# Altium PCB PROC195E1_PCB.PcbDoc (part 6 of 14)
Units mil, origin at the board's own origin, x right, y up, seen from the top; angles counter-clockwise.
Board outline 3110.24 x 2500 mil, 10 copper layers (Top Layer, L02_GND1, L03_SIG1, L04_GND2, L05_PWR1, L06_PWR2, L07_GND3, L08_SIG2, L09_GND4, Bottom Layer), stack 66.407 mil thick; 571 components, 538 nets, 6726 pads, 1286 vias.
Unrouted connection lines stored in the file: 4.
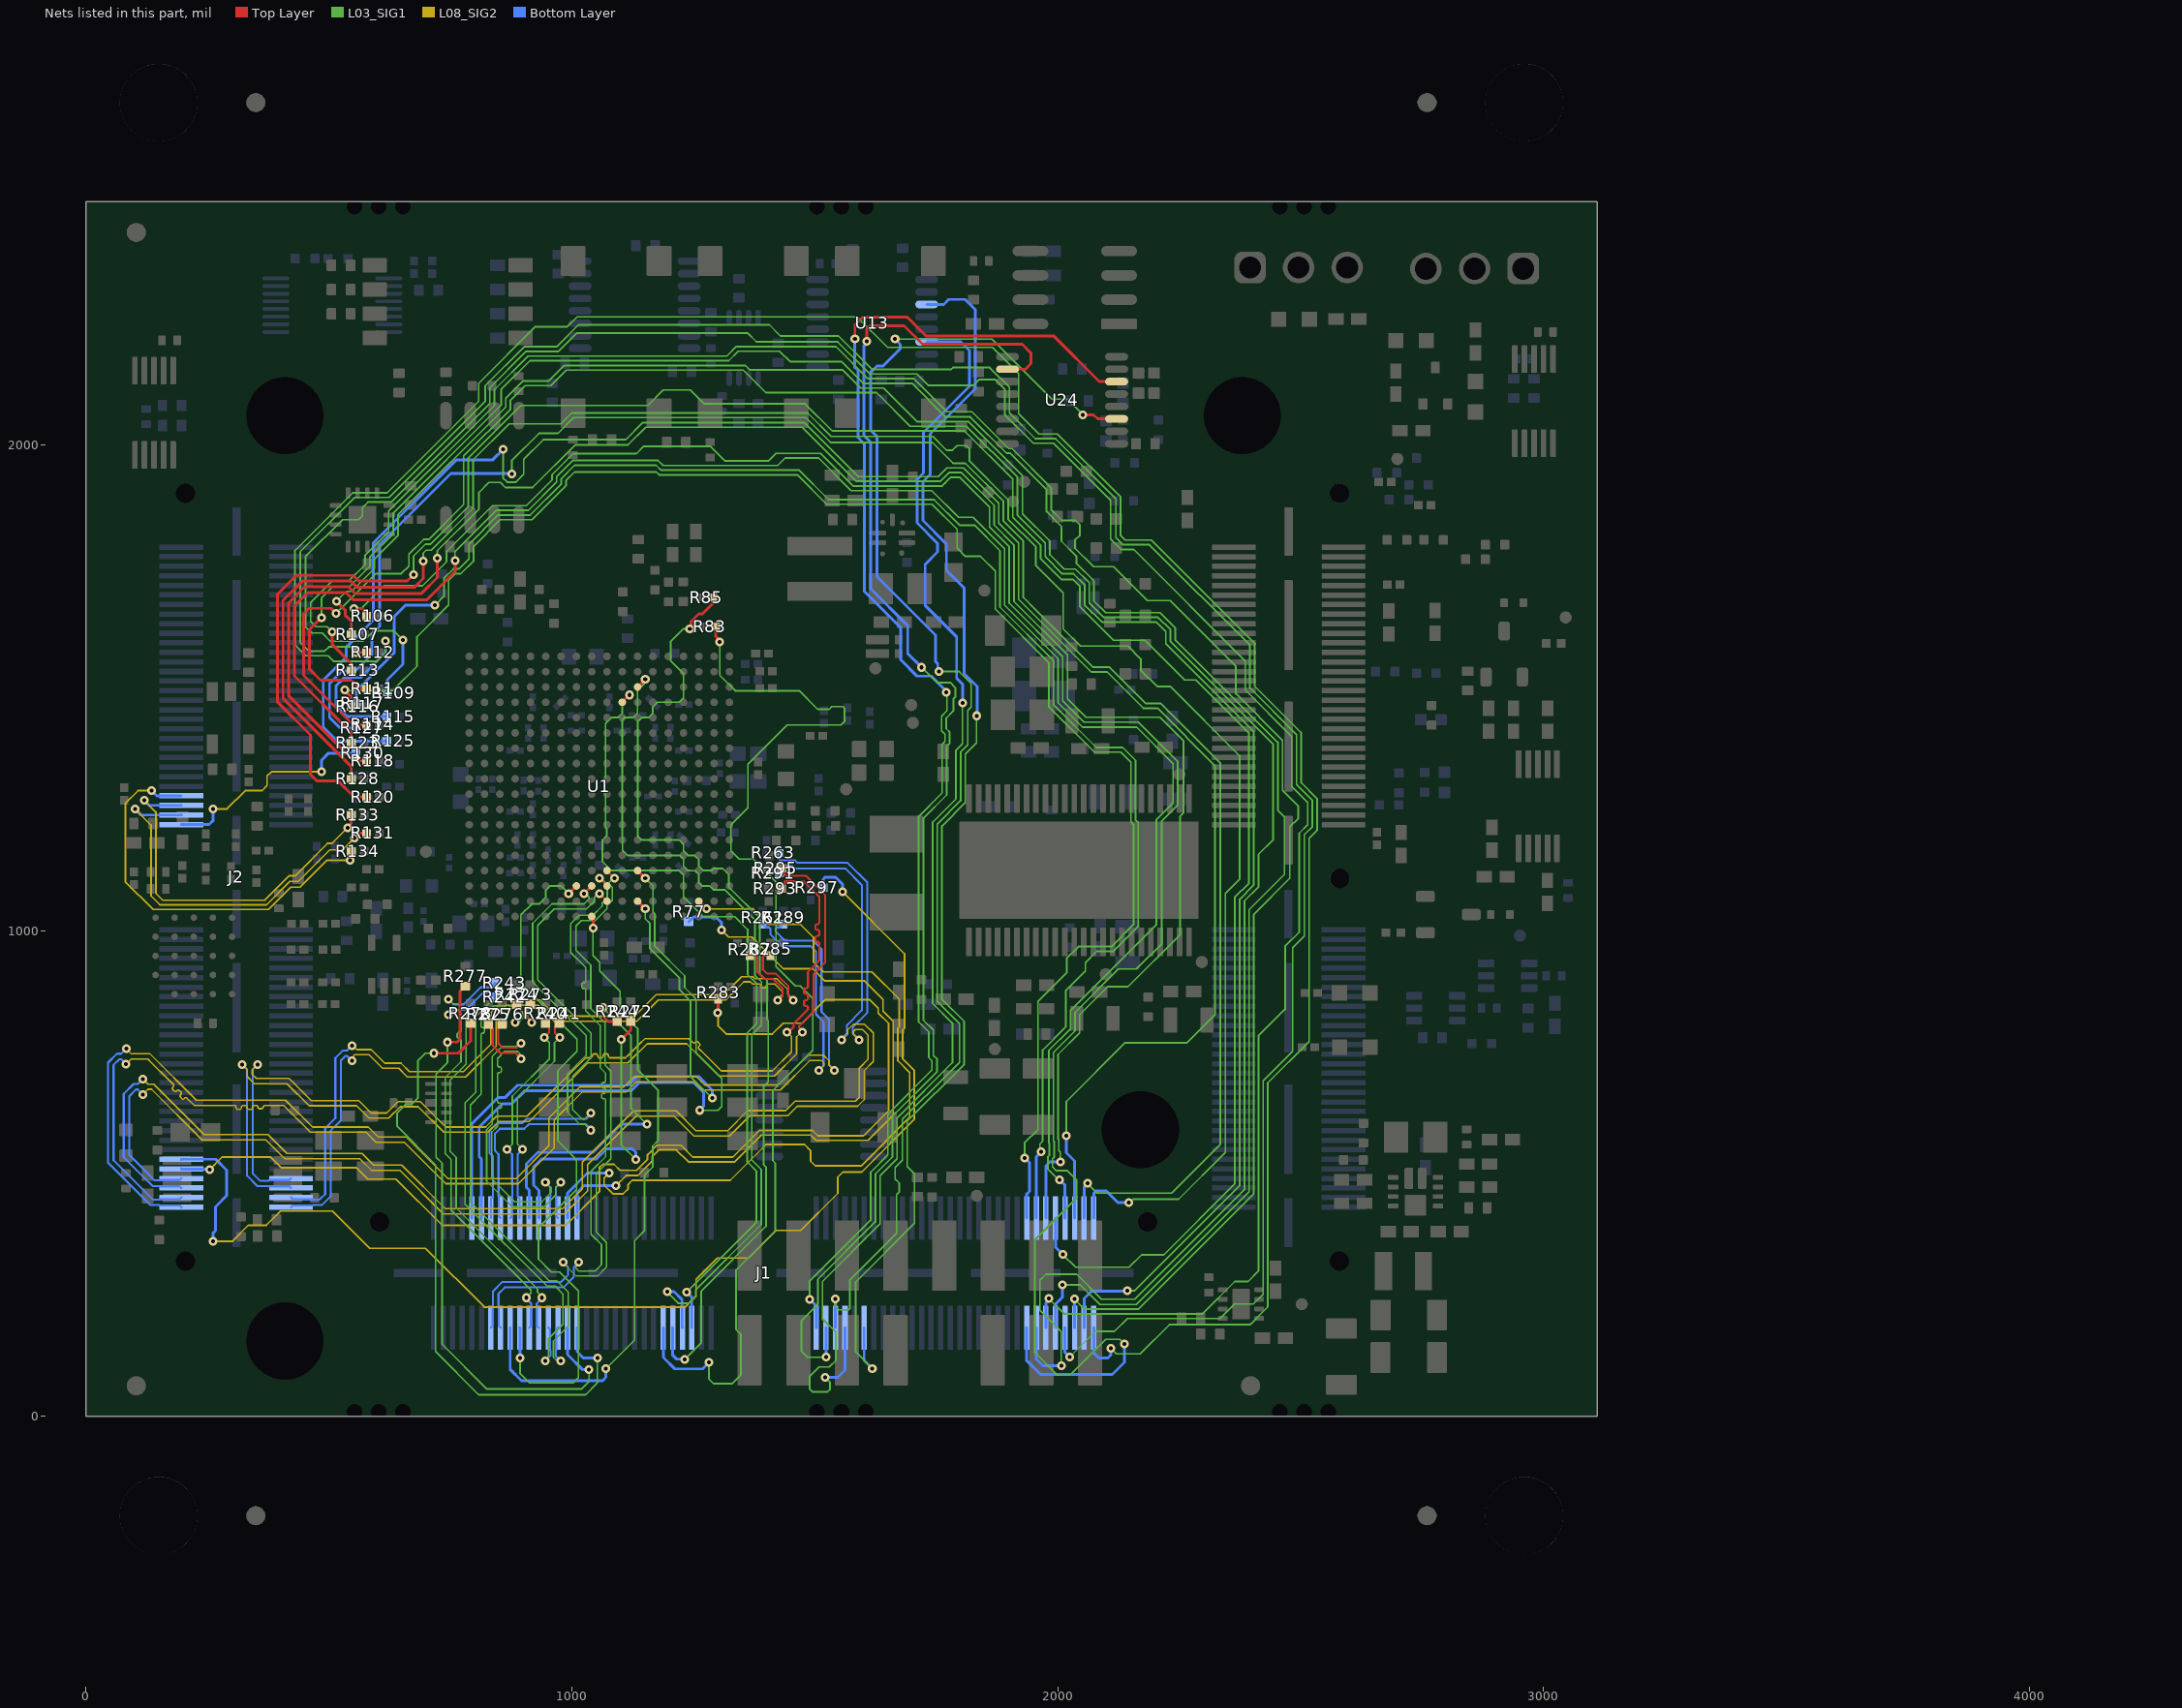
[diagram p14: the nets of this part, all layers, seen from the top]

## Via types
v1: diameter 18, hole 8, Top Layer to Bottom Layer, tented both sides, 1226 vias
v2: diameter 19.68, hole 7.87, Top Layer to Bottom Layer, tented top, 54 vias
v3: diameter 19.68, hole 7.87, Top Layer to Bottom Layer, 4 vias
v4: diameter 19.68, hole 7.87, Top Layer to Bottom Layer, tented both sides, 2 vias

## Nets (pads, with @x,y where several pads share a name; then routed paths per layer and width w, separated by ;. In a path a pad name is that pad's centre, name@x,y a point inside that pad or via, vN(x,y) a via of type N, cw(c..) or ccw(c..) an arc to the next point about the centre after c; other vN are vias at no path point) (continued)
AM26x_ADC1_AIN4: J1.112 U1.U12 | length 1226.5
  Top Layer w5.8: U1.U12@1135.62,1060.47 v1(1151.37,1044.72)
  L03_SIG1 w3.6: v1(1151.37,1044.72) 1151.37,1024.19 1161,1014.56 1161,987.34 1161,962.91 1221.8,902.12 1221.8,878.19 1244.36,855.63 1244.36,700.1 v1(1289.38,655.08)
  Bottom Layer w5.8: J1.112@794.59,408.19 794.59,602.56 848.85,656.83 863.53,656.83 888.51,681.81 1115.55,681.81 1133.49,699.75 1261.01,699.75 1289.38,671.38 v1(1289.38,655.08)
AM26x_ADC1_AIN5: J1.110 U1.R12 | length 1342.4
  Top Layer w5.8: U1.R12@1135.62,1123.46 v1(1151.37,1107.71)
  L03_SIG1 w3.6: v1(1151.37,1107.71) 1167.11,1091.97 1167.11,1038.26 1170.6,1034.77 1170.6,987.34 1170.6,968.59 1232.6,906.59 1232.6,882.66 1255.85,859.41 1255.85,748.28 1308.72,695.41 1308.72,638.19 1300.57,630.04 v1(1263.62,630.04)
  Bottom Layer w5.8: J1.110@814.27,408.19 814.27,530.28 809.62,534.93 809.62,595.44 858,643.83 877.03,643.83 903.21,670.01 1122.14,670.01 1138.87,686.75 1251.45,686.75 1271.28,666.92 1271.28,639.01 1263.62,631.35 v1(1263.62,630.04)
AM26x_ADC2_AIN0_P: J1.107 U1.R10 | length 1314.8
  Top Layer w4.25: U1.R10@1072.63,1123.46 v1(1088.33,1107.76)
  L03_SIG1 w3.2: v1(982.63,317.32) 982.63,315.79 1009.55,288.87 1053.08,288.87 1071.92,307.71 1071.92,358.2 1050.49,379.63 1050.49,500.19 1080.65,530.35 1080.65,538.21 1080.65,649.97 1080.65,710.89 1069.01,722.53 1069.01,809.38 1039.25,839.15 1039.25,928.88 1008.83,959.29 1008.83,982.91 1008.83,1009.82 1019.92,1020.91 1048.24,1020.91 1072.98,1045.65 1072.98,1051.87 1083.76,1062.65 1083.76,1088.94 1077.98,1094.71 1077.98,1100.45 1085.25,1107.71 v1@1088.38,1107.71
  Bottom Layer w4.25: J1.107@833.96,182.59 837.33,185.96 837.33,227.11 838.1,227.88 838.1,257.45 857.64,276.99 978.34,276.99 992.77,291.42 992.77,307.18 v1(982.63,317.32)
AM26x_ADC2_AIN1_N: J1.105 U1.T10 | length 1308.8
  Top Layer w4.25: v1(1056.88,1108.28) 1061.37,1103.79 1066.51,1098.65 1072.63,1092.53 U1.T10@1072.63,1091.97
  L03_SIG1 w3.2: v1(1014.31,317.32) 1014.31,313.8 1008.56,308.05 1008.56,304.99 1013.99,299.57 1048.65,299.57 1061.22,312.14 1061.22,353.77 1039.79,375.19 1039.79,504.62 1069.95,534.78 1069.95,649.97 1069.95,651.57 1067.71,653.81 1064.19,653.81 1061.95,656.05 1061.95,662.77 1064.19,665.01 1067.71,665.01 1069.95,667.25 1069.95,673.97 1067.71,676.21 1064.19,676.21 1061.95,678.45 1061.95,685.17 1064.19,687.41 1067.71,687.41 1069.95,689.65 1069.95,693.13 1069.95,706.45 1058.31,718.09 1058.31,804.95 1028.55,834.72 1028.55,877.5 1028.55,879.1 1026.31,881.34 1022.79,881.34 1020.55,883.58 1020.55,890.3 1022.79,892.54 1026.31,892.54 1028.55,894.78 1028.55,907.52 1028.55,924.45 998.13,954.86 998.13,1014.26 1015.49,1031.61 1043.81,1031.61 1062.28,1050.08 1062.28,1056.3 1073.06,1067.08 1073.06,1084.5 1067.28,1090.28 1067.28,1101.01 1060.01,1108.28 v1(1056.88,1108.28)
  Bottom Layer w4.25: J1.105@853.64,182.59 850.27,185.96 850.27,227.11 849.5,227.88 849.5,252.72 862.37,265.59 983.06,265.59 1004.17,286.7 1004.17,307.18 v1(1014.31,317.32)
AM26x_ADC2_AIN2_P: J1.108 U1.U10 | length 1079
  Top Layer w4.25: v1(1057.56,1076.11) 1057.56,1075.54 U1.U10@1072.63,1060.47
  L03_SIG1 w3.2: v1(1039.54,624.87) 1027.04,612.38 1020.95,612.38 1002.21,631.12 1002.21,700.59 1040.11,738.49 1040.11,788.73 930.42,898.43 930.42,987.34 930.42,1010.85 963.91,1044.35 1030.21,1044.35 1046.6,1060.74 1046.6,1068.73 1053.99,1076.11 v1(1057.56,1076.11)
  Bottom Layer w4.25: J1.108@833.96,408.19 833.96,447.69 837.33,451.06 837.33,452.71 838.1,453.48 838.1,534.77 830.82,542.05 830.82,586.96 847.53,603.67 897.84,603.67 906.9,612.73 1029.39,612.73 v1@1039.54,622.87
AM26x_ADC2_AIN3_N: J1.106 U1.T9 | length 1078.2
  Top Layer w4.25: v1(1025.38,1076.22) U1.T9@1041.13,1091.97
  L03_SIG1 w3.2: v1@1025.11,1076.5 1028.13,1076.5 1035.9,1068.73 1035.9,1065.17 1025.77,1055.05 959.48,1055.05 919.72,1015.28 919.72,987.34 919.72,893.99 1029.41,784.3 1029.41,742.92 991.51,705.02 991.51,626.68 1016.51,601.68 1027.04,601.68 v1(1039.54,589.18)
  Bottom Layer w4.25: J1.106@853.64,408.19 850.27,411.56 850.27,452.71 849.5,453.48 849.5,539.49 842.22,546.77 842.22,582.24 852.25,592.27 902.57,592.27 911.62,601.33 1029.39,601.33 v1@1039.54,591.18
AM26x_ADC2_AIN4: J1.103 U1.V9 | length 1346.8
  Top Layer w5.8: U1.V9@1041.13,1028.97 1043.04,1027.07 1043.04,1021.86 1044.29,1020.6 v1(1044.29,1005.17)
  L03_SIG1 w3.6: v1(1044.29,1005.17) 1044.29,1005.32 1043.67,1005.95 1043.67,987.34 1043.67,948.58 1057.65,934.6 1057.65,917.3 1099.48,875.47 1099.48,834.73 1135.68,798.53 1135.68,713.78 1177.67,671.8 1177.67,567.57 1166.85,556.75 1166.85,513.26 1149.71,496.12 1149.71,381.83 1129.31,361.43 1129.31,157.23 v1(1070.18,98.1)
  Bottom Layer w5.8: J1.103@873.33,182.59 873.33,97.1 896.88,73.55 1063.53,73.55 1070.18,80.2 v1(1070.18,98.1)
AM26x_ADC2_AIN5: J1.101 U1.T8 | length 1496.2
  Top Layer w5.8: v1(993.89,1076.22) U1.T8@1009.64,1091.97
  L03_SIG1 w3.6: v1(894.01,120.54) 894.01,87.98 912.86,69.13 1003.18,69.13 1013.84,79.8 1013.84,258.55 975.17,297.22 958.28,297.22 931.91,323.6 931.91,388.51 1009.86,466.46 1009.86,528.72 971.5,567.08 971.5,711.69 1011.01,751.2 1011.01,776.67 895.43,892.26 895.43,987.34 895.43,1032.2 917.94,1054.72 932.88,1054.72 946.64,1068.49 946.64,1082.67 956.09,1092.11 977.99,1092.11 v1(993.89,1076.22)
  Bottom Layer w5.8: J1.101@893.01,182.59 893.51,182.09 893.51,121.04 v1(894.01,120.54)
AM26x_ADC3_AIN0_P: J1.104 R240.1 | length 455
  Top Layer w4.25: v1(943.37,780.19) 953.77,790.59 953.77,802.1 946.54,809.32 R240.1@946.13,809.32
  L03_SIG1 w3.2: v1(867.33,549.63) 877.9,560.2 877.9,659.43 953.87,735.4 953.87,769.7 v1(943.37,780.19)
  Bottom Layer w4.25: v1(867.33,549.63) 877.39,539.56 877.39,481.13 877.51,481 877.51,453.48 876.7,452.67 876.7,411.56 J1.104@873.33,408.19
AM26x_ADC3_AIN1_N: J1.102 R241.1 | length 455.3
  Top Layer w4.25: R241.1@974.13,809.32 973.64,809.32 965.17,800.85 965.17,790.09 v1(975.06,780.19)
  L03_SIG1 w3.2: v1(899.01,549.63) 888.6,560.04 888.6,655 964.57,730.96 964.57,769.7 v1(975.06,780.19)
  Bottom Layer w4.25: J1.102@893.01,408.19 893.01,447.69 889.64,451.06 889.64,452.76 888.91,453.48 888.91,485.73 888.79,485.85 888.79,539.4 v1(899.01,549.63)
AM26x_ADC3_AIN2_P: J1.99 R242.1 | length 911
  L03_SIG1 w3.2: v1(746.53,826.69) 749.37,829.53 749.37,836.05 752.22,838.9 763.82,838.9 772.3,830.43 772.3,804.33 772.3,792.18 770.06,789.94 766.54,789.94 764.3,787.7 764.3,780.98 766.54,778.74 770.06,778.74 772.3,776.5 772.3,774.9 772.3,730.25 739.43,697.37 739.43,541.09 751.6,528.92 751.6,425.01 916.12,260.49 916.12,254.48 906.7,245.06 v1(906.7,244.39)
  Bottom Layer w4.25: v1(746.53,826.69) 756.68,836.84 782.52,836.84 817.52,871.84 832.89,871.84 841.43,863.3 R242.1@841.43,862.81 ; v1(906.7,244.39) 906.7,242.42 916.84,232.27 916.84,227.88 916.07,227.11 916.07,185.96 J1.99@912.7,182.59
AM26x_ADC3_AIN3_N: J1.97 R243.1 | length 913.6
  L03_SIG1 w3.2: v1(746.53,858.38) 746.65,858.38 755.42,849.6 768.26,849.6 783,834.86 783,774.9 783,725.81 750.13,692.94 750.13,545.52 762.3,533.35 762.3,429.45 929.62,262.13 929.62,255.14 938.38,246.38 v1(938.38,244.39)
  Bottom Layer w4.25: v1(746.53,858.38) 756.68,848.24 777.8,848.24 812.8,883.24 832.89,883.24 841.43,891.77 R243.1@841.43,892.26 ; J1.97@932.38,182.59 929.01,185.96 929.01,227.11 928.24,227.88 928.24,232.27 938.38,242.42 v1(938.38,244.39)
AM26x_ADC3_AIN4: J1.100 R244.1 | length 725.1
  Top Layer w5.8: v1(1064.84,842.2) 1064.84,823.57 1075.39,813.02 R244.1@1093.49,813.02
  L03_SIG1 w3.6: v1(1064.84,842.2) 1064.84,840.79 1122.13,783.49 1122.13,633.72 1154.18,601.68 v1(1154.42,601.68)
  Bottom Layer w5.8: J1.100@912.7,408.19 912.7,465.47 906.69,471.47 906.69,519.68 930.82,543.82 1043.56,543.82 1101.42,601.68 v1(1154.42,601.68)
AM26x_ADC3_AIN5: J1.98 R272.1 | length 657.7
  Top Layer w5.8: v1(1102.28,775.94) 1121.49,795.15 R272.1@1121.49,813.02
  L03_SIG1 w3.6: v1(1102.28,775.94) 1102.28,558.62 v1(1132.07,528.84)
  Bottom Layer w5.8: J1.98@932.38,408.19 932.38,465.33 921.91,475.79 921.91,513.65 937.79,529.53 1050.43,529.53 1071.92,551.02 1124.64,551.02 1132.07,543.59 v1(1132.07,528.84)
AM26x_ADC4_AIN0_P: J1.95 R273.1 | length 1103.1
  Top Layer w4.25: R273.1@914.72,847.7 914.23,847.7 907.01,840.47 907.01,838.1 906.88,837.98 906.88,821.92 917.81,810.99 v1(917.81,810.9)
  L03_SIG1 w3.2: v1(917.81,810.9) 917.81,811.99 909.52,820.28 909.52,837.18 890.5,856.2 835.88,856.2 802.49,822.81 802.49,774 802.49,667.44 780.67,645.62 780.67,436.81 949.36,268.12 965.8,268.12 981.85,252.07 981.85,189.86 951.84,159.85 951.84,123.91 945.57,117.64 v1(945.57,114.4)
  Bottom Layer w4.25: v1(945.57,114.4) 945.57,114.5 956.21,125.15 956.21,135.38 955.44,136.15 955.44,179.21 J1.95@952.07,182.59
AM26x_ADC4_AIN1_N: J1.93 R274.1 | length 1104.1
  Top Layer w4.25: v1(883.64,810.9) 883.64,810.99 895.48,822.83 895.48,839.43 887.22,847.7 R274.1@886.72,847.7
  L03_SIG1 w3.2: v1(883.64,810.9) 886.47,813.74 893.92,813.74 898.82,818.64 898.82,832.75 886.07,845.5 881,845.5 874.48,845.5 872.24,843.26 872.24,839.74 870,837.5 863.28,837.5 861.04,839.74 861.04,843.26 858.8,845.5 846,845.5 840.31,845.5 813.19,818.38 813.19,804.33 813.19,802.48 815.43,800.24 818.56,800.24 820.8,798 820.8,791.28 818.56,789.04 815.43,789.04 813.19,786.8 813.19,774 813.19,663.01 791.37,641.19 791.37,441.25 953.79,278.82 970.23,278.82 992.55,256.51 992.55,185.43 962.54,155.42 962.54,121.49 966.8,117.23 974.42,117.23 v1(977.25,114.4)
  Bottom Layer w4.25: J1.93@971.75,182.59 968.38,179.21 968.38,138.07 967.61,137.3 967.61,123.69 976.9,114.4 v1(977.25,114.4)
AM26x_ADC4_AIN2_P: J1.96 R275.1 | length 709.4
  Top Layer w4.25: R275.1@828.55,807.2 829.05,807.2 837.43,798.82 837.43,763.45 852.92,747.96 884.02,747.96 v1(895.5,736.48)
  L03_SIG1 w3.2: v1(895.5,736.48) 892.74,739.24 892.74,747.16 888.76,751.13 861.55,751.13 847.17,736.75 847.17,726.43 847.17,721.48 849.41,719.24 852.93,719.24 855.17,717 855.17,710.28 852.93,708.04 849.41,708.04 847.17,705.8 847.17,693 847.17,657.65 847.17,647.48 849.41,645.24 852.93,645.24 855.17,643 855.17,636.28 852.93,634.04 849.41,634.04 847.17,631.8 847.17,619 847.17,597.15 835.79,585.77 835.79,488.52 882.28,442.03 938.54,442.03 956.56,460.05 956.56,471.25 v1(946.07,481.75)
  Bottom Layer w4.25: v1(946.07,481.75) 956.21,471.6 956.21,453.48 955.44,452.71 955.44,411.56 J1.96@952.07,408.19
AM26x_ADC4_AIN3_N: J1.94 R276.1 | length 712.5
  Top Layer w4.25: R276.1@856.55,807.2 856.06,807.2 848.84,799.97 848.84,797.49 848.83,768.17 857.64,759.36 886.33,759.36 895.14,768.16 v1(895.5,768.16)
  L03_SIG1 w3.2: v1(895.5,768.16) 892.32,768.16 885.99,761.83 857.12,761.83 836.47,741.19 836.47,619 836.47,601.59 825.09,590.21 825.09,484.09 877.85,431.33 942.97,431.33 967.26,455.62 967.26,471.25 v1(977.75,481.75)
  Bottom Layer w4.25: J1.94@971.75,408.19 968.38,411.56 968.38,452.71 967.61,453.48 967.61,471.6 v1(977.75,481.75)
AM26x_ADC4_AIN4: J1.91 R277.1 | length 1262.4
  Top Layer w5.8: v1(744.54,770.51) 764.37,770.51 770.58,776.72 770.58,875.09 774.16,878.67 774.16,879.16 780.61,885.61 R277.1@781.1,885.61
  L03_SIG1 w3.6: v1(744.54,770.51) 744.54,728.51 721.03,704.99 721.03,533.47 733.37,521.12 733.37,148.79 825.88,56.28 1020.17,56.28 1035.7,71.8 v1(1035.7,96.04)
  Bottom Layer w5.8: J1.91@991.44,182.59 991.44,127.57 1022.96,96.04 v1(1035.7,96.04)
AM26x_ADC4_AIN5: J1.89 R278.1 | length 1345.5
  Top Layer w5.8: v1(716.8,747.61) 766.55,747.61 791.99,773.05 R278.1@791.99,809.54
  L03_SIG1 w3.6: v1(716.8,747.61) 698.71,747.61 683.62,732.52 683.62,655.66 671.1,643.15 659.3,643.15 640.89,624.74 640.89,596.97 719.9,517.96 719.9,133.53 808.79,44.64 1028.44,44.64 1052.88,69.08 v1(1052.88,119.98)
  Bottom Layer w5.8: J1.89@1011.12,182.59 1011.12,133.02 1024.16,119.98 v1(1052.88,119.98)
AM26x_ADC_CAL0: J1.92 U1.U16 | length 1719.5
  Top Layer w5.8: U1.U16@1261.61,1060.47 v1(1277.35,1044.72)
  L08_SIG2 w3.6: v1(1077.33,500.71) 1066.76,490.13 1066.76,476.05 1084.43,458.38 1106.02,458.38 1116.09,468.45 1116.09,477.71 1124.36,485.99 1326.17,485.99 1399.93,559.75 1478.87,559.75 1491.42,547.2 1491.42,525.85 1501.64,515.63 1595.56,515.63 1695.6,615.68 1695.6,707.74 1671.23,732.11 1671.23,798.87 1674.04,801.68 1674.04,858.96 1617.94,915.06 1517.94,915.06 1497.5,935.5 1497.5,986.27 1470.68,1013.09 1404.76,1013.09 1390.29,1027.56 1373.13,1044.72 v1(1277.35,1044.72)
  Bottom Layer w5.8: J1.92@991.44,408.19 991.44,459.79 1032.36,500.71 v1(1077.33,500.71)
AM26x_ADC_CAL1: J1.90 R77.2 | length 1534.8
  L08_SIG2 w3.6: v1(1091.39,475.18) 1112.23,496.01 1136.58,496.01 1165.55,524.99 1165.55,534.64 1179.46,548.55 1215.52,548.55 1239.86,524.2 1335.68,524.2 1390.57,579.09 1491.67,579.09 1502.7,568.07 1609.55,568.07 1661.63,620.15 1661.63,813.15 1640.44,834.34 1640.44,858.56 1602.57,896.43 1521.3,896.43 1496.2,921.53 1435.43,921.53 1370.26,986.69 1322.93,986.69 v1(1308.62,1001.01)
  Bottom Layer w5.8: J1.90@1011.12,408.19 1011.12,461.09 1011.5,461.09 1025.59,475.18 v1(1091.39,475.18) ; R77.2@1240.7,1018.36 1241.2,1018.36 1247.65,1024.81 1247.65,1025.01 1251.04,1028.4 1296.52,1028.4 1308.62,1016.31 v1(1308.62,1001.01)
AM26x_ADC_CAL2: J2.112 R283.2 | length 2345.2
  Top Layer w5.8: v1(1300.77,831.09) 1301.35,831.68 R283.2@1301.35,858.8
  L08_SIG2 w3.6: v1(254.81,507.87) 280.96,534.02 380.12,534.02 402.02,512.12 556.44,512.12 580.13,488.42 638.35,488.42 733.42,393.35 987.85,393.35 1056.94,462.45 1056.94,512.12 1063.67,518.85 1087.08,518.85 1099.58,506.35 1133.34,506.35 1155.95,528.96 1155.95,538.61 1175.49,558.15 1224.97,558.15 1249.31,533.8 1331.7,533.8 1386.59,588.69 1495.65,588.69 1506.67,577.67 1600.4,577.67 1652.03,629.31 1652.03,809.17 1630.84,830.36 1630.84,839.91 1612.88,857.87 1522.3,857.87 1473.85,809.41 1435.32,809.41 1412.97,787.06 1318.19,787.06 1301.14,804.1 1301.14,830.72 v1(1300.77,831.09)
  Bottom Layer w5.8: J2.112@196.81,509.59 197.67,508.73 253.95,508.73 v1(254.81,507.87)
AM26x_ADC_CAL3: J2.110 R297.2 | length 2625
  L08_SIG2 w3.6: v1(261.78,360.35) 301.13,360.35 334.14,393.36 371.47,393.36 400.8,422.69 507.73,422.69 584.28,346.14 699.18,346.14 820.19,225.13 1233.76,225.13 1256.1,247.47 1256.1,282.5 1299.67,326.07 1363.27,326.07 1420.2,382.99 1471.26,382.99 1547.42,459.15 1547.42,492.16 1558.28,503.02 1596.53,503.02 1705.2,611.7 1705.2,712.01 1680.84,736.38 1680.84,794.9 1684.84,798.9 1684.84,952.33 v1@1557.13,1080.05
  Bottom Layer w5.8: J2.110@196.81,529.27 196.89,529.35 267.62,529.35 289.85,507.12 289.85,454.51 266.85,431.51 266.85,382.49 262.4,378.05 262.4,360.97 v1(261.78,360.35) ; R297.2@1517.59,1088.61 1517.59,1106.1 1521.64,1110.14 1542.54,1110.14 1557.13,1095.55 v1(1557.13,1080.06)
AM26x_ADC_R0_AIN0_P: J2.120 R289.2 | length 2586.7
  L08_SIG2 w3.2: v1(83.18,756.77) 93.67,746.28 132.35,746.28 227.56,651.08 411.2,651.08 466.58,595.69 581.19,595.69 601.81,575.07 660.03,575.07 745.44,489.67 885.85,489.67 953.27,557.08 953.27,614.65 1016.89,678.27 1107.59,678.27 1129.14,699.81 1255.97,699.81 1262.69,693.09 ; 1268.05,687.74 1262.69,693.09 ; v1(1540.63,712.53) 1539.38,712.53 1529.43,722.48 1529.43,732.11 1517.89,743.64 1486.05,743.64 1424.74,682.33 1297.87,682.33 1297.82,682.38 1273.4,682.38 1262.69,693.09
  Bottom Layer w4.25: v1(83.18,756.77) 73.03,746.63 64.38,746.63 45.92,728.17 45.92,522.47 133.39,434.99 151.52,434.99 152.29,434.22 193.44,434.22 J2.120@196.81,430.85 ; R289.2@1435.67,1013.55 1435.67,1012.76 1429.53,1006.62 1422.52,1006.62 1420.11,1004.2 1420.11,997.63 1438.58,979.16 1496.64,979.16 1514.02,961.78 1514.02,832.7 1529.53,817.19 1529.53,723.62 v1(1540.63,712.53)
AM26x_ADC_R0_AIN1_N: J2.118 R261.1 | length 2573.6
  L08_SIG2 w3.2: v1(82.26,725.09) 83.18,725.09 93.67,735.58 127.92,735.58 134.57,728.93 171.77,691.73 172.9,690.6 180.82,682.68 180.82,679.51 178.33,677.02 178.33,673.85 183.08,669.1 186.25,669.1 188.74,671.59 191.91,671.59 196.66,666.84 196.66,663.67 194.17,661.18 194.17,658.01 198.92,653.26 202.09,653.26 204.58,655.75 207.75,655.75 207.84,655.66 208.97,654.53 223.12,640.38 233.64,640.38 274,640.38 288.13,640.38 294.34,640.38 307.14,640.38 309.38,638.14 309.38,634.62 311.62,632.38 318.34,632.38 320.58,634.62 320.58,638.14 322.82,640.38 329.54,640.38 331.78,638.14 331.78,634.62 334.02,632.38 340.74,632.38 342.98,634.62 342.98,638.14 345.22,640.38 351.94,640.38 354.18,638.14 354.18,635.74 356.42,633.5 363.14,633.5 365.38,635.74 365.38,638.14 367.62,640.38 391.42,640.38 406.77,640.38 462.15,584.99 576.76,584.99 597.38,564.37 655.6,564.37 741,478.97 890.28,478.97 963.97,552.65 963.97,610.21 1021.32,667.57 1112.03,667.57 1133.57,689.11 1251.54,689.11 1258.26,682.39 1263.62,677.04 1268.97,671.68 1293.38,671.68 1293.43,671.63 1429.17,671.63 1490.48,732.94 1513.46,732.94 1518.73,727.68 1518.73,722.31 v1(1508.94,712.53)
  Bottom Layer w4.25: v1(82.26,725.09) 82.26,726 73.03,735.23 69.1,735.23 57.32,723.45 57.32,527.19 138.12,446.39 151.52,446.39 152.29,447.16 193.44,447.16 J2.118@196.81,450.53 ; R261.1@1393.15,1013.55 1393.15,1012.76 1399.29,1006.62 1406.29,1006.62 1408.71,1004.2 1408.71,992.91 1433.86,967.76 1491.92,967.76 1502.62,957.06 1502.62,827.98 1518.13,812.47 1518.13,721.72 v1(1508.94,712.53)
AM26x_ADC_R0_AIN2_P: J2.119 R287.2 | length 1654
  Top Layer w4.25: R287.2@1366.8,948.19 1379.81,948.19 1382.22,945.78 1382.22,933.1 1382.15,933.02 1382.15,915.16 1397.03,900.28 1414.93,900.28 1434.14,881.07 1434.14,865.08 1426.06,857 v1(1424,857)
  L08_SIG2 w3.2: v1(548.11,731.75) 550.94,734.58 550.94,741.98 553.41,744.45 582.81,744.45 610.67,716.58 644.18,716.58 661.75,699.01 781.67,699.01 844.76,762.1 844.76,826.69 864.2,846.14 931.03,846.14 964.04,813.14 1134.07,813.14 1178.28,857.35 1316.87,857.35 1354.12,894.6 1367.88,894.6 1372.5,889.98 1373.94,889.98 1386.74,889.98 1388.98,887.74 1388.98,884.22 1391.22,881.98 1397.94,881.98 1400.18,884.22 1400.18,887.74 1402.42,889.98 1409.14,889.98 1418.09,889.98 1434,874.07 1434,869 1424,859 v1(1424,857)
  Bottom Layer w4.25: J2.119@422.41,430.85 425.79,434.22 466.94,434.22 467.7,434.99 486.04,434.99 503.96,452.9 503.96,588.06 525.05,609.15 525.05,732.91 534.04,741.89 537.97,741.89 v1(548.11,731.75)
AM26x_ADC_R0_AIN3_N: J2.117 R285.2 | length 1655.3
  Top Layer w4.25: R285.2@1408.9,948.56 1408.53,948.19 1396.04,948.19 1393.62,945.78 1393.62,928.38 1393.55,928.3 1393.55,919.88 1401.75,911.68 1419.65,911.68 1445.54,885.79 1445.54,865.08 1453.62,857 v1(1455.68,857)
  L08_SIG2 w3.2: v1(548.11,763.44) 549.2,763.44 557.49,755.15 587.24,755.15 615.1,727.28 648.61,727.28 666.18,709.71 777.23,709.71 834.06,766.53 834.06,831.13 859.77,856.84 935.47,856.84 968.47,823.84 1129.64,823.84 1173.84,868.05 1312.44,868.05 1349.69,905.3 1372.31,905.3 1376.93,900.68 1422.52,900.68 1444.7,878.5 1444.7,869 1455.68,858.02 v1(1455.68,857)
  Bottom Layer w4.25: J2.117@422.41,450.53 425.79,447.16 466.94,447.16 467.7,446.39 481.32,446.39 492.56,457.62 492.56,592.78 513.65,613.88 513.65,737.63 529.31,753.29 537.97,753.29 v1(548.11,763.44)
AM26x_ADC_R1_AIN0_P: J2.116 R263.1 | length 2823.5
  L08_SIG2 w3.2: v1(117.4,694.46) 127.89,683.97 139.98,683.97 243.85,580.11 375.19,580.11 414.07,541.22 568.49,541.22 592.18,517.52 650.4,517.52 740.5,427.43 980.76,427.43 1021.87,468.53 1021.87,523.13 1127.72,628.98 1214.9,628.98 1256,587.88 1320.52,587.88 1362.17,629.53 1440.17,629.53 1459.78,649.13 1584.03,649.13 1591.65,656.75 1591.65,716.87 1609.75,734.97 1609.75,785 1598.35,796.4 1583.9,796.4 1579.81,792.3 1579.81,786.36 v1(1591.41,774.75)
  Bottom Layer w4.25: v1(117.4,694.46) 107.26,684.32 98.6,684.32 78.17,663.9 78.17,533.55 119.22,492.51 137.37,474.36 151.41,474.36 152.18,473.59 193.44,473.59 J2.116@196.81,470.22 ; R263.1@1427.06,1159.67 1427.06,1147.05 1429.55,1144.56 1459,1144.56 1464.16,1139.4 1567.72,1139.4 1608.4,1098.72 1608.4,831.28 1578,800.88 1578,789 1591.41,775.59 v1(1591.41,774.75)
AM26x_ADC_R1_AIN1_N: J2.114 R291.2 | length 2819.8
  L08_SIG2 w3.2: v1(117.4,662.78) 127.89,673.27 135.55,673.27 239.41,569.41 370.75,569.41 409.64,530.52 564.06,530.52 587.75,506.82 645.97,506.82 736.07,416.73 985.2,416.73 1032.57,464.1 1032.57,518.7 1132.15,618.28 1210.47,618.28 1251.57,577.18 1324.95,577.18 1366.6,618.83 1444.6,618.83 1464.21,638.43 1588.46,638.43 1602.35,652.32 1602.35,712.44 1620.45,730.54 1620.45,789.43 1602.78,807.1 1579.47,807.1 1568.27,795.89 1568.27,787.04 v1(1555.87,774.64)
  Bottom Layer w4.25: v1(117.4,662.78) 107.26,672.92 103.32,672.92 89.57,659.17 89.57,538.28 123.94,503.91 142.09,485.76 151.41,485.76 152.18,486.53 193.44,486.53 J2.114@196.81,489.9 ; R291.2@1427.06,1118.06 1427.06,1130.68 1429.55,1133.16 1454.28,1133.16 1459.44,1128 1563,1128 1597,1094 1597,836 1566.6,805.6 1566.6,789 1555.87,778.27 v1(1555.87,774.64)
AM26x_ADC_R1_AIN2_P: J2.115 R295.2 | length 2161.5
  Top Layer w4.25: R295.2@1432.46,1128.18 1437.29,1123.35 1437.29,1115.18 1439.71,1112.77 1482.19,1112.77 1521.31,1073.65 1521.31,933.91 1497.54,910.14 1497.54,832.99 1468.09,803.54 1468.09,800.12 1474.92,793.29 v1(1474.92,790.83)
  L08_SIG2 w3.2: v1@321.91,724.19 332.04,714.06 332.04,699.83 346.87,685 414.15,685 459.74,639.41 ; 459.85,639.41 557.3,639.41 582.82,613.89 623.49,613.89 647.14,637.54 684.07,637.54 736.61,584.99 827.6,584.99 849.74,607.13 912.83,607.13 1033.1,727.41 1115.51,727.41 1155.11,767 1236.77,767 1303.24,700.53 1417.2,700.53 ; 1412.77,700.53 1417.2,700.53 ; v1(1474.92,790.83) 1472.55,790.83 1462.72,781 1462.72,746.05 1417.2,700.53
  Bottom Layer w4.25: v1(321.91,724.42) 332.05,714.28 332.05,495.58 353.75,473.89 377.05,473.89 377.35,473.59 419.04,473.59 J2.115@422.41,470.22
AM26x_ADC_R1_AIN3_N: J2.113 R293.2 | length 2159.3
  Top Layer w4.25: R293.2@1431.49,1086.35 1437.29,1092.15 1437.29,1098.95 1439.71,1101.37 1477.47,1101.37 1509.91,1068.93 1509.91,1030.29 1509.91,1015.92 1507.42,1013.43 1504.36,1013.43 1501.91,1010.98 1501.91,1003.63 1504.36,1001.18 1507.46,1001.18 1509.91,998.73 1509.91,991.38 1507.46,988.93 1504.36,988.93 1501.91,986.48 1501.91,979.13 1504.36,976.68 1507.42,976.68 1509.91,974.19 1509.91,953.16 1509.91,938.63 1486.14,914.87 1486.14,887.84 1486.14,884.05 1483.65,881.56 1480.59,881.56 1478.14,879.11 1478.14,871.76 1480.59,869.31 1483.69,869.31 1486.14,866.86 1486.14,859.51 1483.69,857.06 1480.59,857.06 1478.14,854.61 1478.14,847.26 1480.59,844.81 1483.65,844.81 1486.14,842.33 1486.14,840.2 1486.14,837.71 1456.69,808.26 1456.69,801.97 1445.55,790.83 v1(1443.24,790.83)
  L08_SIG2 w3.2: v1(353.6,724.42) 342.74,713.57 342.74,704.26 351.3,695.7 418.58,695.7 464.17,650.11 ; 464.28,650.11 561.74,650.11 587.26,624.59 619.06,624.59 642.71,648.24 688.5,648.24 741.04,595.69 823.17,595.69 845.31,617.83 908.39,617.83 1028.67,738.11 1038.12,738.11 1039.91,738.11 1042.15,740.35 1042.15,743.87 1044.39,746.11 1051.11,746.11 1053.35,743.87 1053.35,740.35 1055.59,738.11 1062.31,738.11 1064.55,740.35 1064.55,743.87 1066.79,746.11 1073.51,746.11 1075.75,743.87 1075.75,740.35 1077.99,738.11 1090.79,738.11 1109.46,738.11 1111.08,738.11 1115.65,742.68 1142.25,769.28 1147.99,775.01 1150.68,777.7 1155.88,777.7 1188.61,777.7 1195.94,777.7 1241.2,777.7 1248.9,770 1250.03,768.87 1253.2,768.87 1255.69,771.36 1258.86,771.36 1263.61,766.61 1263.61,763.44 1261.12,760.95 1261.12,757.78 1272.66,746.24 1273.79,745.11 1283.2,735.7 1300.19,718.71 1307.67,711.23 1350.04,711.23 1412.77,711.23 1452.02,750.48 1452.02,782.05 v1(1443.24,790.83)
  Bottom Layer w4.25: v1(353.6,724.42) 343.45,714.28 343.45,500.31 358.47,485.29 376.54,485.29 377.78,486.53 419.04,486.53 J2.113@422.41,489.9
AM26x_EPWM0_A: J1.15 R106.1 | length 4313.8
  Top Layer w5.8: v1(551.63,1663.21) 568.87,1663.21 572.27,1659.81 572.27,1652.55 R106.1@577.64,1647.18
  L03_SIG1 w3.6: v1(551.63,1663.21) 567.25,1663.21 613.76,1709.73 692.66,1709.73 742.27,1759.34 742.27,1779.8 836.96,1874.48 906.67,1874.48 959.48,1927.29 959.48,1938.36 1002.89,1981.78 1133.5,1981.78 1148.69,1996.96 1284.76,1996.96 1314.8,1966.92 1405.29,1966.92 1420.69,1982.32 1511.79,1982.32 1573.01,1921.1 1578.9,1915.21 1762.59,1915.21 1768.48,1921.1 1780.42,1933.03 1797.88,1933.03 1859.67,1871.24 1859.67,1830.79 1900.49,1789.96 1900.49,1673.84 2010.5,1563.83 2010.5,1473.17 2054.54,1429.13 2165.83,1429.13 2247.15,1347.82 2247.15,1258.8 2214.27,1225.93 2214.27,973.16 2161.99,920.88 2125.12,920.88 2035.7,831.46 2035.7,793.46 1991.32,749.08 1991.32,567.02 1992.7,565.64 1992.7,533.62 1989.34,530.25 1989.34,513.08 1996.31,506.11 2019.69,506.11 2039.29,486.51 2039.29,450.05 1953.14,363.89 1953.14,131.33 1999.5,84.97 2025.31,84.97 2099.22,158.87 2128.21,158.87 v1(2137.55,149.54)
  Bottom Layer w5.8: J1.15@1936.44,182.59 1936.42,114.66 1964.73,86.35 2112.43,86.35 2137.55,111.47 v1(2137.55,149.54)
AM26x_EPWM0_B: J1.13 R107.1 | length 4477.5
  Top Layer w5.8: v1(515.67,1677.82) 533.73,1659.76 533.73,1649.58 546.52,1636.79 R107.1@546.52,1609.96
  L03_SIG1 w3.6: v1(515.67,1677.82) 536.1,1698.25 546.98,1698.25 594.35,1745.63 594.35,1765.09 642.39,1813.12 642.39,1855.43 864.33,2077.38 864.33,2095.49 900.17,2131.33 952.85,2131.33 984.92,2163.41 1357.06,2163.41 1366.59,2153.87 1557.93,2153.87 1594.94,2116.86 1641.42,2116.86 1710.55,2047.73 1816.38,2047.73 1927.49,1936.63 1927.49,1858 1983.94,1801.55 1983.94,1773.73 2013.54,1744.13 2036.72,1744.13 2065.03,1715.82 2065.03,1674.68 2095.04,1644.67 2206.8,1644.67 2232.2,1619.27 2232.2,1594.97 2443.43,1383.74 2443.43,1187.03 2413.13,1156.72 2413.13,1089.67 2384.39,1060.93 2384.39,467 2158.95,241.57 2090.24,241.57 2039.1,292.7 1975.9,292.7 1963.46,280.26 1963.46,218.47 2007.47,174.47 v1(2007.47,104.25)
  Bottom Layer w5.8: J1.13@1956.12,182.59 1956.12,118.28 1970.15,104.25 v1(2007.47,104.25)
AM26x_EPWM1_A: J1.11 R109.1 | length 4909.5
  L03_SIG1 w3.6: v1(652.78,1597.9) 633.82,1616.86 591.76,1616.86 570.45,1595.55 503.2,1595.55 486.36,1612.38 465.64,1612.38 452.14,1625.88 452.14,1769.61 528.28,1845.75 561.43,1845.75 569.5,1853.82 569.5,1870.4 580.94,1881.84 628.06,1881.84 831.42,2085.19 831.42,2117.22 906.4,2192.21 973,2192.21 1010.89,2230.1 1361.79,2230.1 1379.99,2211.91 1547.37,2211.91 1613.62,2145.66 1710.25,2145.66 1733.48,2122.43 1826.43,2122.43 1838.03,2134.03 1871.58,2134.03 1890.94,2114.67 1890.94,2062.06 1950.01,2002.99 1991.76,2002.99 2109.14,1885.61 2109.14,1806.01 2130.64,1784.51 2156.61,1784.51 2385.96,1555.17 2385.96,1495.52 2481.83,1399.65 2481.83,1296.42 2514.58,1263.67 2514.58,1218.04 2497.03,1200.48 2497.03,996.53 2468,967.5 2468,838 2413.19,783.19 2413.19,299.19 2391.8,277.8 2364.59,277.8 2298.06,211.28 2013.32,211.28 v1(1981.97,242.62)
  Bottom Layer w5.8: R109.1@620.53,1489.43 620.53,1516.22 652.53,1548.21 652.53,1597.65 v1(652.78,1597.9) ; J1.11@1975.81,182.59 1975.81,233.59 1981.97,239.75 v1(1981.97,242.62)
AM26x_EPWM1_B: J1.9 R111.1 | length 4499.6
  Top Layer w5.8: v1(485.07,1644.24) 460,1619.17 460,1538.73 483.3,1515.43 546.16,1515.43 563.3,1498.29 R111.1@577.66,1498.29
  L03_SIG1 w3.6: v1(485.07,1644.24) 485.07,1683.88 509.04,1707.85 543,1707.85 584.75,1749.6 584.75,1769.07 632.79,1817.1 632.79,1859.41 854.73,2081.35 854.73,2113.39 914.35,2173.01 1323.2,2173.01 1342.82,2192.63 1427.68,2192.63 1449.14,2171.17 1554.64,2171.17 1599.35,2126.46 1700.01,2126.46 1769.14,2057.33 1820.36,2057.33 1895.21,1982.48 1902.28,1982.48 1977.13,1907.63 1977.13,1862.43 2007.9,1831.66 2007.9,1801.38 2038.61,1770.67 2038.61,1755.81 2074.63,1719.79 2074.63,1678.66 2099.02,1654.27 2210.78,1654.27 2241.8,1623.25 2241.8,1598.95 2453.03,1387.72 2453.03,1247.73 2466.79,1233.98 2466.79,1115.87 2393.99,1043.07 2393.99,463.03 2161.44,230.48 2086.85,230.48 2046.61,270.72 v1(2009.71,270.72)
  Bottom Layer w5.8: J1.9@1995.85,182.94 1995.95,183.04 1995.95,231.44 2009.71,245.2 v1(2009.71,270.72)
AM26x_EPWM2_A: J1.7 R112.1 | length 4805.5
  Top Layer w5.8: v1(555.61,1572.69) R112.1@577.64,1572.71
  L03_SIG1 w3.6: v1(555.61,1572.69) 544.31,1583.99 500.35,1583.99 491.81,1575.45 458.76,1575.45 441.34,1592.86 441.34,1779.64 553.14,1891.44 624.09,1891.44 821.82,2089.17 821.82,2121.2 902.42,2201.81 969.02,2201.81 1013.95,2246.74 1406.89,2246.74 1429.74,2223.89 1548.96,2223.89 1617.59,2155.26 1781.23,2155.26 1784.88,2158.91 1860.27,2158.91 1900.54,2118.65 1900.54,2066.04 1953.99,2012.59 1995.74,2012.59 2120.01,1888.31 2120.01,1814.45 2120.01,1808.72 2134.62,1794.11 2188.89,1794.11 2395.56,1587.44 2395.56,1499.5 2491.43,1403.62 2491.43,1300.39 2524.18,1267.65 2524.18,1214.06 2507.57,1197.45 2507.57,988.96 2483.78,965.17 2483.78,751.78 2422.79,690.79 2422.79,251.77 2402.43,231.41 2363.97,231.41 2334.24,201.68 2143.62,201.68 2117.03,175.08 2077.65,175.08 v1(2024.82,122.25)
  Bottom Layer w5.8: J1.7@2015.18,182.59 2015.18,131.89 v1(2024.82,122.25)
AM26x_EPWM2_B: J1.5 R113.1 | length 4419
  Top Layer w5.8: v1(507.44,1615.07) 507.44,1588.56 546.52,1549.48 R113.1@546.52,1535.51
  L03_SIG1 w3.6: v1(507.44,1615.07) v1(507.44,1615.07) 497.05,1625.52 474.08,1625.52 462.94,1636.67 462.94,1675.33 506.87,1719.26 540.84,1719.26 575.15,1753.58 575.15,1773.05 623.19,1821.08 623.19,1863.38 841.02,2081.21 841.02,2113.25 910.38,2182.61 1319.22,2182.61 1338.84,2202.23 1543.47,2202.23 1609.64,2136.06 1703.98,2136.06 1772.24,2067.81 1823.46,2067.81 1899.18,1992.08 1906.26,1992.08 1986.73,1911.61 1986.73,1866.41 2008.86,1844.28 2036.76,1844.28 2046,1835.04 2046,1814.08 2035.48,1803.56 2035.48,1787.38 2073.96,1748.9 2115.03,1748.9 2184.47,1679.46 2231.44,1679.46 2366.76,1544.14 2366.76,1487.57 2462.63,1391.69 2462.63,1288.47 2495.38,1255.72 2495.38,1231.25 2477.83,1213.7 2477.83,1107.83 2403.59,1033.59 2403.59,459.05 2165.41,220.88 2055.55,220.88 v1(2034.52,241.91)
  Bottom Layer w5.8: v1(2034.52,241.91) 2034.69,241.74 2034.69,182.76 J1.5@2034.86,182.59
AM26x_EPWM3_A: J1.3 R114.1 | length 4385.8
  Top Layer w5.8: v1(515.39,1652.79) 504.77,1663.41 459.56,1663.41 448.2,1652.05 448.2,1525.52 549.87,1423.85 R114.1@577.66,1423.85
  L03_SIG1 w3.6: v1(515.39,1652.79) 515.39,1653.08 597.08,1734.78 649.45,1734.78 665.02,1750.35 665.02,1774.74 695.51,1805.23 705.93,1805.23 777.85,1877.15 777.85,1976.9 873.93,2072.98 873.93,2091.52 904.1,2121.69 956.78,2121.69 988.9,2153.81 1353.08,2153.81 1399.62,2107.26 1627.41,2107.26 1696.54,2038.13 1812.4,2038.13 1917.27,1933.27 1917.27,1854.65 1974.34,1797.57 1974.34,1769.75 2009.56,1734.53 2013.12,1734.53 2032.74,1734.53 2055.43,1711.84 2055.43,1670.71 2091.07,1635.07 2202.83,1635.07 2222.6,1615.3 2222.6,1591 2403.19,1410.4 2403.19,1093.32 2374.79,1064.91 2374.79,475.27 2158.46,258.94 v1(2142.98,258.94)
  Bottom Layer w5.8: J1.3@2054.55,182.59 2054.55,242.83 2069.95,258.24 2142.28,258.24 v1(2142.98,258.94)
AM26x_EPWM3_B: J1.1 R115.1 | length 5241.7
  L03_SIG1 w3.6: v1(616.98,1596.42) 616.98,1571.94 599.22,1554.17 510.52,1554.17 498.85,1565.85 452.49,1565.85 430.54,1587.8 430.54,1782.41 549.16,1901.04 620.11,1901.04 808.44,2089.36 808.44,2126.2 925.24,2243 991,2243 1011.37,2263.37 1587.22,2263.37 1650.09,2200.49 1866.03,2200.49 1919.65,2146.87 1919.65,2064.24 1961.7,2022.19 1999.72,2022.19 2129.61,1892.29 2129.61,1812.69 2138.6,1803.71 2192.99,1803.71 2405.16,1591.54 2405.16,1503.48 2501.03,1407.6 2501.03,1304.37 2533.78,1271.63 2533.78,1206.18 2517.38,1189.78 2517.38,771.52 2432.39,686.53 2432.39,225.39 2396,189 2230,189 2169.86,128.86 2121.3,128.86 v1(2109.49,140.68)
  Bottom Layer w5.8: v1(616.98,1596.42) 616.98,1572.09 565.85,1520.95 532.35,1520.95 514.71,1503.31 514.71,1463.85 537.98,1440.58 R115.1@619.6,1440.58 ; J1.1@2074.23,182.59 2074.23,130.77 2084.54,120.46 2103.22,120.46 2109.49,126.74 v1(2109.49,140.68)
AM26x_EPWM4_A: J1.16 R116.1 | length 3382.8
  Top Layer w5.8: v1(532.61,1495) 546.52,1481.08 R116.1@546.52,1461.07
  L03_SIG1 w3.6: v1(532.61,1495) 533.81,1493.8 631.17,1493.8 681.67,1544.29 681.67,1605.13 746.75,1670.21 746.75,1720.99 760.44,1734.68 771.87,1734.68 798.27,1761.08 798.27,1791.18 852.78,1845.68 918.6,1845.68 988.28,1915.36 988.28,1926.43 1005.71,1943.86 1174.24,1943.86 1179.98,1938.12 1463.99,1938.12 1524.61,1877.51 1741.69,1877.51 1792.92,1826.28 1792.92,1787.77 1810.43,1770.26 1841.46,1770.26 1871.69,1740.03 1871.69,1661.91 1981.7,1551.9 1981.7,1461.24 2075.62,1367.32 2130.07,1367.32 2150.71,1346.68 2150.71,1223.67 2156.15,1218.23 2156.15,1012.37 2110.94,967.17 2042.8,967.17 2018.61,942.98 2018.61,913.34 1959.44,854.17 1959.44,590.37 1932,562.94 v1(1932,532.12)
  Bottom Layer w5.8: v1(1932,532.12) 1941.79,522.34 1941.79,463.18 1936.44,457.83 J1.16@1936.44,408.19
AM26x_EPWM4_B: J1.14 R117.1 | length 3338
  L03_SIG1 w3.6: v1(718.83,1669.61) 737.15,1687.92 737.15,1725.17 756.26,1744.28 767.89,1744.28 788.67,1765.06 788.67,1792.12 788.67,1795.15 848.8,1855.28 851.83,1855.28 914.62,1855.28 978.68,1919.34 978.68,1930.41 1006.17,1957.9 1173.77,1957.9 1183.96,1947.72 1467.97,1947.72 1528.58,1887.11 1745.66,1887.11 1798.21,1834.56 1828.75,1834.56 1881.29,1782.01 1881.29,1665.89 1991.3,1555.88 1991.3,1465.21 2079.6,1376.92 2134.05,1376.92 2160.31,1350.66 2160.31,1227.65 2165.75,1222.21 2165.75,1008.39 2114.92,957.57 2080.55,957.57 2057.21,934.23 2057.21,917.05 2016.5,876.34 2016.5,801.41 1969.04,753.95 1969.04,566.22 1963.58,560.75 1963.58,547.28 v1(1966.3,544.55)
  Bottom Layer w5.8: R117.1@556.57,1467.83 556.57,1493.29 634.88,1571.6 634.88,1646.47 658.02,1669.61 v1(718.83,1669.61) ; J1.14@1956.12,408.19 1956.12,534.37 v1(1966.3,544.55)
AM26x_EPWM5_A: J1.12 R118.1 | length 4039
  Top Layer w5.8: R118.1@577.66,1349.4 551.51,1349.4 417.8,1483.11 417.8,1674.77 450.55,1707.52 540.44,1707.52 553.85,1694.11 691.11,1694.11 723.44,1726.44 v1(723.44,1766.21)
  L03_SIG1 w3.6: v1(723.44,1766.21) 723.44,1781.93 809.18,1867.67 809.18,1902.05 829.5,1922.37 853.23,1922.37 863.63,1911.97 919.51,1911.97 1007.45,1999.91 1116.04,1999.91 1152.13,2036 1474.33,2036 1585.52,1924.81 1758.62,1924.81 1764.51,1930.7 1776.44,1942.63 1801.85,1942.63 1869.27,1875.22 1869.27,1834.76 1910.09,1793.94 1910.09,1677.82 2020.1,1567.81 2020.1,1477.14 2058.18,1439.07 2210.51,1439.07 2259.14,1390.44 2259.14,1242.82 2252.14,1235.82 2252.14,992.01 2144.82,884.69 2103.15,884.69 2045.3,826.84 2045.3,789.48 2000.92,745.1 2000.92,571 2002.3,569.62 2002.3,547.53 2005.52,544.31 2005.52,524.14 v1(2006.14,523.53)
  Bottom Layer w5.8: J1.12@1975.81,408.19 1975.81,516.14 1983.2,523.53 v1(2006.14,523.53)
AM26x_EPWM5_B: J1.10 R120.1 | length 4632.6
  Top Layer w5.8: R120.1@577.66,1274.96 552.17,1274.96 518.65,1308.47 475.5,1308.47 462.51,1321.46 462.51,1402.62 394.2,1470.93 394.2,1691.77 433.55,1731.12 550.21,1731.12 561.52,1719.82 661.57,1719.82 v1(674.62,1732.86)
  L03_SIG1 w3.6: v1(674.62,1732.86) 674.62,1770.76 699.48,1795.63 709.91,1795.63 787.45,1873.17 787.45,1972.93 895.57,2081.05 1156.9,2081.05 1188.59,2112.74 1244.06,2112.74 1272.72,2084.08 1480.56,2084.08 1536.1,2028.53 1808.43,2028.53 1907.67,1929.29 1907.67,1850.67 1964.74,1793.59 1964.74,1765.78 2007.68,1722.84 2030.85,1722.84 2045.83,1707.86 2045.83,1666.73 2115.02,1597.54 2179.84,1597.54 2261.31,1516.06 2283.96,1516.06 2393.59,1406.43 2393.59,1097.29 2364.45,1068.15 2364.45,478.52 2218.5,332.56 2172.55,332.56 2147.01,307.02 2037.11,307.02 v1(2010.71,333.42)
  Bottom Layer w5.8: J1.10@1995.49,408.19 1995.49,348.64 v1(2010.71,333.42)
AM26x_EPWM6_A: J1.8 R123.1 | length 3756.4
  Top Layer w5.8: R123.1@546.52,1386.62 546.52,1407.18 429.6,1524.11 429.6,1668.18 457.14,1695.72 535.55,1695.72 550.16,1681.11 702.21,1681.11 759.93,1738.83 v1(759.93,1761.81)
  L03_SIG1 w3.6: v1(759.93,1761.81) 759.93,1779.99 844.83,1864.88 910.65,1864.88 969.08,1923.31 969.08,1934.38 1002.2,1967.5 1177.75,1967.5 1187.93,1957.32 1423.88,1957.32 1439.28,1972.72 1507.81,1972.72 1574.92,1905.61 1740.74,1905.61 1795.66,1850.69 1826.19,1850.69 1890.89,1785.99 1890.89,1669.86 2000.9,1559.85 2000.9,1469.19 2051.34,1418.75 2162.64,1418.75 2237.55,1343.84 2237.55,1262.78 2203.39,1228.62 2203.39,1012.73 2026.1,835.44 2026.1,797.43 1981.72,753.06 1981.72,563.05 1983.1,561.67 1983.1,537.6 1979.74,534.23 1979.74,509.11 2002.02,486.83 v1(2004.29,486.83)
  Bottom Layer w5.8: v1(2004.29,486.83) 2015.18,475.95 J1.8@2015.18,408.19
AM26x_EPWM6_B: J1.6 R125.1 | length 4047.3
  L03_SIG1 w3.6: v1(858.63,1991.04) 858.63,1931.52 866.95,1923.2 885.12,1923.2 901.19,1939.27 901.19,1970.11 941.8,2010.71 1111.57,2010.71 1146.46,2045.6 1478.3,2045.6 1589.5,1934.41 1754.64,1934.41 1772.47,1952.23 1805.83,1952.23 1878.87,1879.19 1878.87,1838.74 1919.69,1797.92 1919.69,1681.79 2069.09,1532.4 2101.63,1532.4 2176.27,1457.75 2205.41,1457.75 2323.61,1339.55 2323.61,826.62 2266.29,769.3 2138.86,769.3 2017.72,648.16 v1(2017.72,577.96)
  Bottom Layer w5.8: R125.1@619.29,1390.16 517.2,1390.16 488.71,1418.66 488.71,1515.36 535.72,1562.38 535.72,1582.83 591.92,1639.02 591.92,1798.29 762.73,1969.1 837.56,1969.1 858.63,1990.17 v1(858.63,1991.04) ; v1(2017.72,577.96) 2017.72,542.89 2034.86,525.76 J1.6@2034.86,408.19
AM26x_EPWM7_A: J1.4 R127.1 | length 3901.8
  L03_SIG1 w3.6: v1(876.67,1940) 876.67,1967.49 932.72,2023.53 971.78,2023.53 1004.05,2055.81 1481.67,2055.81 1532.76,2004.72 1741.87,2004.72 1784.76,1961.83 1809.81,1961.83 1888.47,1883.17 1888.47,1842.72 1929.29,1801.89 1929.29,1685.77 1957.41,1657.65 2073.06,1542 2106.91,1542 2181.56,1467.35 2212.79,1467.35 2334.55,1345.59 2334.55,559.55 2234.6,459.6 2081.49,459.6 v1(2061.21,479.87)
  Bottom Layer w5.8: R127.1@555.81,1417.55 522.68,1417.55 501.71,1438.52 501.71,1508.69 526.97,1533.95 554.21,1533.95 588.56,1568.3 588.56,1609.91 604.92,1626.27 604.92,1794.6 751.29,1940.97 875.7,1940.97 v1(876.67,1940) ; J1.4@2054.55,408.19 2054.55,473.21 v1(2061.21,479.87)
AM26x_EPWM7_B: J1.2 R128.1 | length 4276.7
  Top Layer w5.8: R128.1@546.52,1312.18 546.52,1337.65 406,1478.18 406,1679.65 445.67,1719.32 545.33,1719.32 557.54,1707.11 677.17,1707.11 694.46,1724.41 v1(694.46,1760.54)
  L03_SIG1 w3.6: v1(694.46,1760.54) 694.46,1777.03 700.45,1783.01 710.94,1783.01 797.05,1869.12 797.05,1968.95 871.08,2042.98 977.64,2042.98 1000.08,2065.41 1485.65,2065.41 1533.87,2017.19 1742.98,2017.19 1771.39,1988.78 1783.41,1988.78 1792.8,1998.17 1812.35,1998.17 1818.24,1992.28 1818.24,1966.98 1898.07,1887.15 1898.07,1846.69 1955.14,1789.62 1955.14,1751.42 2011.38,1695.18 2011.38,1621.01 2046.79,1585.6 2144.58,1585.6 2171.14,1559.04 2171.14,1535.94 2204.45,1502.63 2231.77,1502.63 2374.39,1360.01 2374.39,1105.25 2345.25,1076.1 2345.25,543.38 2249,447.12 2155.2,447.12 2148.11,440.03 v1(2145.89,440.03)
  Bottom Layer w5.8: J1.2@2074.23,408.19 2074.23,458.71 2079.99,464.47 2099.33,464.47 2123.77,440.03 v1(2145.89,440.03)
AM26x_EPWM8_A: J2.60 R130.1 | length 459.1
  L08_SIG2 w3.6: v1(262.41,1250.47) 290.67,1250.47 328.19,1288 362.64,1288 373.26,1298.62 373.26,1318.26 381.9,1326.9 v1(484.98,1326.9)
  Bottom Layer w5.8: J2.60@196.81,1218.37 253.89,1218.37 262.41,1226.88 v1(262.41,1250.47) ; v1(484.98,1326.9) 484.98,1350.53 499.69,1365.25 R130.1@555.92,1365.25
AM26x_EPWM8_B: J2.58 R131.1 | length 804.6
  Top Layer w5.8: v1(553.33,1190.78) 553.33,1192.13 561.71,1200.51 R131.1@577.66,1200.51
  L08_SIG2 w3.6: v1(101.97,1249.92) 134.52,1217.37 134.52,1071.14 152.59,1053.07 371.85,1053.07 420.04,1101.26 437.42,1101.26 502.17,1166.01 528.56,1166.01 v1(553.33,1190.78)
  Bottom Layer w5.8: v1(101.97,1249.92) 113.97,1237.93 196.69,1237.93 J2.58@196.81,1238.05
AM26x_EPWM9_A: J2.56 R133.1 | length 774
  Top Layer w5.8: v1(538.73,1211.48) 538.73,1212.97 546.52,1220.77 R133.1@546.52,1237.73
  L08_SIG2 w3.6: v1(120.12,1268.24) 144.12,1244.24 144.12,1076.88 158.33,1062.67 367.87,1062.67 417.87,1112.67 430.53,1112.67 497.38,1179.51 506.75,1179.51 v1(538.73,1211.48)
  Bottom Layer w5.8: v1(120.12,1268.24) 130.63,1257.74 J2.56@196.81,1257.74
AM26x_EPWM9_B: J2.54 R134.1 | length 839.7
  Top Layer w5.8: v1(544.18,1144.81) 544.18,1160.95 R134.1@546.52,1163.29
  L08_SIG2 w3.6: v1(135.36,1288.07) 107.5,1288.07 81.38,1261.94 81.38,1100.63 138.54,1043.47 375.83,1043.47 421.62,1089.26 441.1,1089.26 496.65,1144.81 v1(544.18,1144.81)
  Bottom Layer w5.8: v1(135.36,1288.07) 146.31,1277.11 J2.54@196.5,1277.11
AM26x_EQEP0_A: J1.71 R83.1 | length 2375
  Top Layer w5.8: R83.1@1296.4,1625.99 1296.4,1605.53 1304.64,1597.29 v1(1304.64,1593.99)
  L03_SIG1 w3.6: v1(1282.43,111.2) 1282.43,77.4 1292.44,67.4 1329.64,67.4 1348.4,86.15 1348.4,168.64 1338.23,178.81 1338.23,301.52 1418.88,382.17 1418.88,521.54 1413.96,526.46 1413.96,671.3 1496.12,753.45 1496.12,860.43 1470.46,886.08 1460.25,886.08 1420.29,926.04 1420.29,1100.78 1373.85,1147.22 1344.79,1147.22 1327.59,1164.43 1327.59,1217.95 1362.67,1253.03 1362.67,1342.85 1443.12,1423.3 1554.02,1423.3 1561.61,1430.89 1561.61,1456.95 1557.65,1460.91 1535.09,1460.91 1529.75,1455.57 1506.43,1455.57 1468.37,1493.63 1336.37,1493.63 1304.64,1525.36 v1(1304.64,1593.99)
  Bottom Layer w5.8: J1.71@1188.29,182.59 1188.49,182.38 1188.49,121.62 1212.18,97.93 1269.16,97.93 v1(1282.43,111.2)
AM26x_EQEP0_B: J1.69 R85.1 | length 2053.3
  Top Layer w5.8: v1(1243.03,1620.86) 1245.37,1623.19 1245.37,1629.65 1245.37,1635.85 1261.45,1651.94 1268.92,1651.94 1289.94,1672.96 R85.1@1289.94,1685.63
  L03_SIG1 w3.6: v1(1232.77,117.78) 1266.59,151.6 1266.59,258.3 1399.68,391.39 1399.68,513.59 1394.76,518.51 1394.76,679.25 1404.32,688.81 1404.32,814.31 1402,816.64 1402,896.55 1387.29,911.26 1387.29,987.34 1387.29,1025.48 1323.25,1089.53 1323.25,1114.9 1310.25,1127.89 1292.32,1127.89 1288.04,1123.61 1270.89,1123.61 1261.75,1132.75 1261.75,1133.06 1261.56,1133.25 1261.56,1145.71 1252.36,1154.91 1239.35,1154.91 1230.06,1164.2 1230.06,1177.21 1220.77,1186.5 1144.86,1186.5 1143.59,1187.78 1141.84,1187.78 1136.86,1192.76 1136.86,1194.65 1135.77,1195.74 1135.77,1429.85 1144.33,1438.42 1157.82,1438.42 1167.07,1447.67 1167.07,1460.58 1176.46,1469.97 1220.86,1469.97 1230.06,1479.16 1230.06,1528.82 1203.88,1554.99 1203.88,1595.77 1228.97,1620.86 v1(1243.03,1620.86)
  Bottom Layer w5.8: J1.69@1208.03,182.53 1208.03,125.83 1216.09,117.78 v1(1232.77,117.78)
AM26x_EQEP0_INDEX: J1.65 U1.D11 | length 1685.7
  Top Layer w5.8: U1.D11@1104.12,1469.92 1104.12,1470.54 v1(1118.57,1484.99)
  L03_SIG1 w3.6: v1(1118.57,1484.99) 1103.98,1470.4 1103.98,1447.71 1094.69,1438.42 1082.06,1438.42 1069.79,1426.14 1069.79,1211.26 1072.39,1208.66 1072.39,1195.74 1063.18,1186.53 1063.18,1142.35 1082.01,1123.51 1221.02,1123.51 1229.99,1114.53 1229.99,1114.28 1230.06,1114.22 1230.06,1101.21 1230,1101.15 1230,1085.51 1230.06,1085.45 1230.06,1069.81 1271.29,1028.58 1335.45,1028.58 1362.07,1001.95 1362.07,987.34 1362.07,909.33 1380.37,891.03 1380.37,808.55 1361.12,789.3 1361.12,523.98 1380.34,504.76 1380.34,399.71 v1(1236.81,256.19)
  Bottom Layer w5.8: v1(1236.81,256.19) 1247.07,245.93 J1.65@1247.07,182.86
AM26x_EQEP0_STROBE: J1.67 U1.C12 | length 1777.6
  Top Layer w5.8: U1.C12@1135.62,1501.41 v1(1151.37,1517.16)
  L03_SIG1 w3.6: v1(1151.37,1517.16) 1148.61,1514.4 1148.61,1506.98 1135.57,1493.94 1135.57,1447.67 1126.38,1438.47 1108.31,1438.47 1104.17,1434.33 1104.17,1195.78 1104.53,1195.42 1104.53,1165.33 1114.95,1154.91 1222.53,1154.91 1230.16,1147.28 1230.16,1132.71 1239.35,1123.51 1243.53,1123.51 1243.63,1123.41 1254.11,1123.41 1261.75,1115.77 1261.75,1098.64 1268.57,1091.82 1283.81,1091.82 1291.58,1084.05 1315.15,1084.05 1376.88,1022.31 1376.88,987.34 1376.88,908.09 1390.43,894.54 1390.43,805.04 1370.72,785.32 1370.72,527.95 1390.08,508.6 1390.08,395.36 1255.07,260.35 1255.07,247.18 1241,233.12 1218.88,233.12 1196.8,255.2 v1(1196.8,256.87)
  Bottom Layer w5.8: v1(1196.8,256.87) 1210.81,256.87 1227.11,240.58 1227.11,183.14 J1.67@1227.66,182.59
AM26x_FSIRX0_CLK: J1.55 U24.3 | length 2922.9
  Top Layer w5.8: v1(2051.81,2061.75) 2073.82,2061.75 2082.33,2053.24 U24.3@2121.29,2053.24
  L03_SIG1 w3.6: v1(1542.89,241.56) 1542.58,241.25 1542.58,226.38 1549.39,219.57 1570.11,219.57 1572.22,221.68 1572.22,280.44 1668.39,376.62 1668.39,456.48 1674.15,462.24 1674.15,480.13 1665.57,488.72 1665.57,512.41 1680.66,527.5 1680.66,611.79 1775.81,706.94 1776.1,706.94 1798.05,728.89 1798.05,808.6 1752.38,854.28 1752.38,1219.27 1800.46,1267.35 1800.46,1367.4 1815.09,1382.02 1815.09,1452.8 1822.03,1459.74 1822.03,1508.74 1797.38,1533.38 v1@1755.57,1533.38 ; v1(1665.51,2217.49) 1864.51,2217.49 1988,2094 2019.56,2094 v1(2051.81,2061.75)
  Bottom Layer w5.8: J1.55@1542.84,182.69 1542.84,241.51 v1(1542.89,241.56) ; v1(1665.51,2217.49) 1676.28,2206.72 1676.28,2197.51 1640.75,2161.98 1627.92,2161.98 1615.53,2149.59 1615.53,2029.61 1628.1,2017.04 1628.1,1728.7 1748.52,1608.28 1748.52,1553.74 1753.22,1549.04 1753.22,1535.73 v1(1755.55,1533.4)
AM26x_FSIRX0_DATA0: J1.59 U24.6 | length 2912.1
  Top Layer w5.8: v1(1582.84,2217.45) 1582.84,2246.13 1599.55,2262.85 1690.58,2262.85 1729.95,2223.48 1992.33,2223.48 2085.8,2130.01 U24.6@2121.29,2130.01
  L03_SIG1 w3.6: v1(1489.22,241.02) 1489.46,241.27 1489.46,278.49 1615.46,404.49 1615.46,503.04 1650.46,538.04 1650.46,622.32 1741.37,713.23 1741.37,732.15 1734.84,738.68 1734.84,791.1 1713.98,811.96 1713.98,1235.18 1762.06,1283.26 1762.06,1383.3 1768.21,1389.45 1768.21,1404.26 1761.01,1411.46 1761.01,1441.45 1772.17,1452.6 1772.17,1488.65 v1(1770.61,1490.2)
  Bottom Layer w5.8: v1(1489.22,241.02) 1489.93,241.02 1503.37,227.59 J1.59@1503.37,182.59 ; v1(1582.84,2217.45) 1582.34,2216.96 1582.34,2159.62 1589.02,2152.94 1589.02,2014.37 1602.1,2001.29 1602.1,1698.07 1677.3,1622.87 1677.3,1556.99 1710.37,1523.91 1739.71,1523.91 1770.61,1493.01 v1(1770.61,1490.2)
AM26x_FSIRX0_DATA1: J1.57 U24.10 | length 2915.4
  Top Layer w5.8: v1(1607.37,2212.64) 1607.37,2238.32 1614.06,2245 1684,2245 1722.23,2206.77 1926.95,2206.77 1945.2,2188.52 1945.2,2166.84 1933.96,2155.6 1928.41,2155.6 ; U24.10@1896.89,2155.6 1927.48,2155.6
  L03_SIG1 w3.6: v1(1523.44,121.99) 1485.14,121.99 1472.47,134.66 1472.47,196.97 1506.33,230.84 1506.33,281.72 1625.06,400.45 1625.06,499.06 1660.06,534.06 1660.06,618.34 1751.85,710.13 1751.85,735.25 1744.44,742.66 1744.44,795.07 1723.58,815.93 1723.58,1231.2 1771.66,1279.28 1771.66,1379.32 1777.81,1385.48 1777.81,1408.6 1770.61,1415.8 1770.61,1437.47 1785.46,1452.33 1785.46,1476.77 1789.48,1480.79 1789.48,1500.04 1778.96,1510.57 1751.45,1510.57 v1(1720.21,1541.81)
  Bottom Layer w5.8: J1.57@1523.05,182.59 1523.24,182.4 1523.24,122.18 v1(1523.44,121.99) ; v1(1607.37,2212.64) 1607.37,2209.34 1601.57,2203.54 1601.57,2018.51 1615.1,2004.98 1615.1,1703.85 1691.5,1627.45 1691.5,1570.47 v1(1720.21,1541.81) v1(1720.21,1541.81)
AM26x_FSITX0_CLK: J1.49 U13.3 | length 2643.1
  L03_SIG1 w3.6: v1(1618.68,98.2) 1584.41,132.47 1584.41,276.84 1705.44,397.86 1705.44,499.4 1690.56,514.28 1690.56,607.82 1807.65,724.91 1807.65,812.9 1761.98,858.57 1761.98,1215.3 1810.06,1263.38 1810.06,1363.42 1833.1,1386.46 v1(1833.1,1442.13)
  Bottom Layer w5.8: J1.49@1601.79,182.59 1601.79,115.09 v1(1618.68,98.2) ; U13.3@1730.57,2288.84 1765.63,2288.84 1775.92,2299.13 1809.73,2299.13 1830.51,2278.35 1830.51,2115.37 1737.68,2022.54 1737.68,1938.82 1722.6,1923.75 1722.6,1844.12 1771.24,1795.48 1771.24,1741.66 1807.54,1705.35 1807.54,1528.91 1834.23,1502.23 1834.23,1443.27 v1(1833.1,1442.13)
AM26x_FSITX0_DATA0: J1.53 U13.6 | length 2747.4
  L03_SIG1 w3.6: v1(1521.11,80.59) 1531.65,70.05 1531.65,55.82 1526.54,50.7 1495.46,50.7 1489.51,56.65 1489.51,82.33 1509.19,102 1530.39,102 1543.48,115.09 1543.48,173.23 1515.93,200.78 1515.93,277.75 1634.66,396.48 1634.66,495.09 1669.66,530.08 1669.66,614.36 1783.41,728.11 1783.41,809.67 1742.78,850.3 1742.78,1223.25 1790.86,1271.33 1790.86,1371.37 1804.21,1384.72 v1(1804.21,1468.81)
  Bottom Layer w5.8: v1(1521.11,80.59) 1547.58,80.59 1562.42,95.43 J1.53@1562.42,182.59 ; U13.6@1730.57,2212.07 1800.64,2212.07 1818.71,2194 1818.71,2120.26 1724.01,2025.56 1724.01,1941.84 1710.8,1928.63 1710.8,1839.23 1753,1797.03 1753,1779.3 1727.29,1753.59 1727.29,1669.24 1792.15,1604.38 1792.15,1519.64 1804.21,1507.58 v1(1804.21,1468.81)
